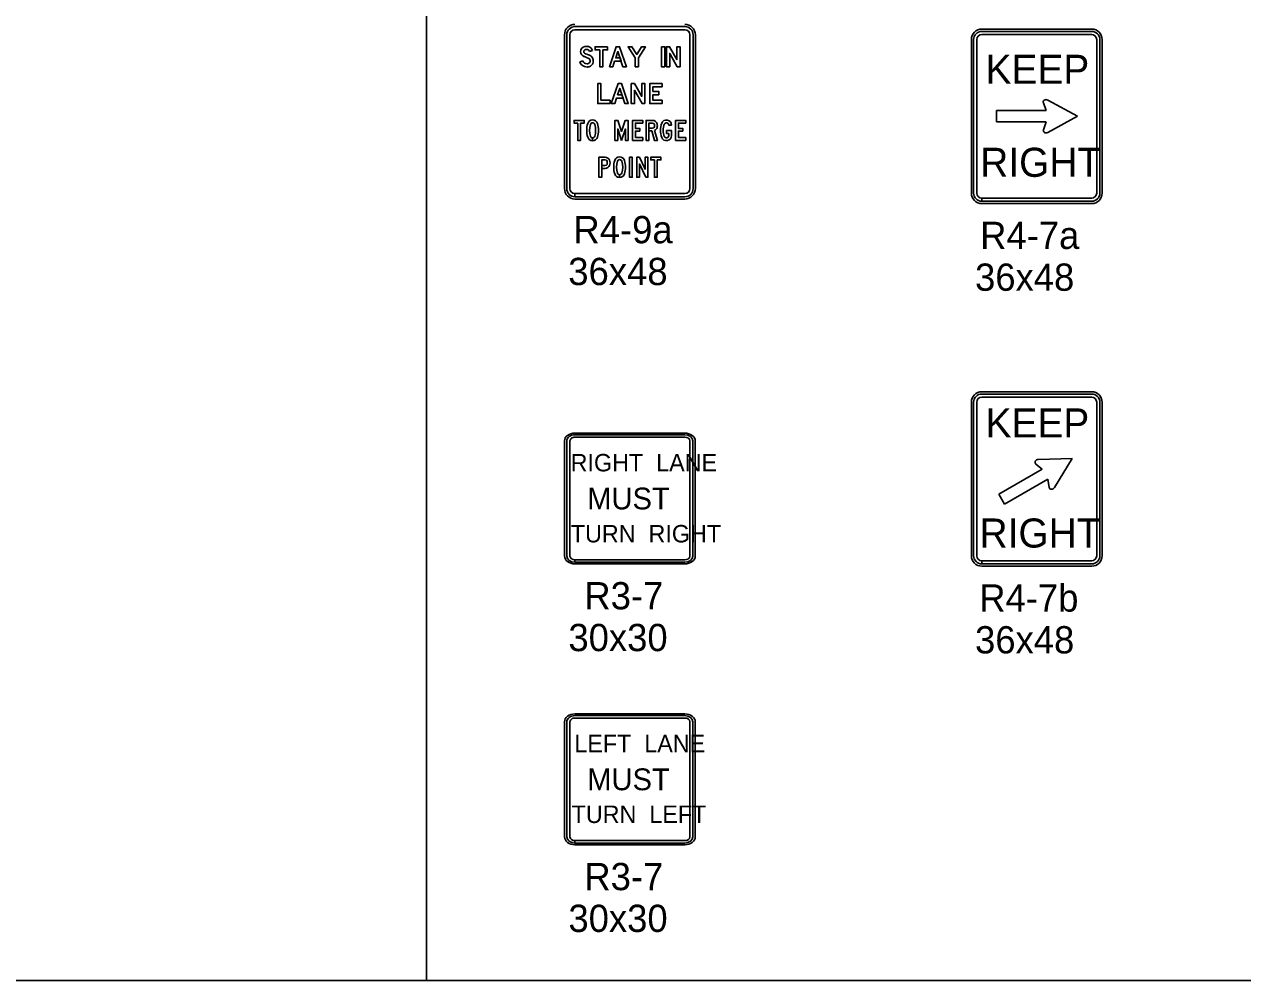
# Model space of a CAD drawing. Extents: x 1458 to 4498, y 17709 to 24109.
# Drawn here: x 3157 to 3828, y 19909 to 20435 of the extents above; entities that cross this region are included whole.
import ezdxf

# ---------------------------------------------------------------- set-up
doc = ezdxf.new("R2010")
doc.units = 0
doc.layers.add('P_ODOT_PLAN_TBlock', color=7, linetype='Continuous')
doc.layers.add('P_TRAF_TCP_General', color=7, linetype='Continuous')

msp = doc.modelspace()

# ---------------------------------------------------------------- linework, layer by layer
at = {"layer": 'P_ODOT_PLAN_TBlock'}
msp.add_line((3378.44, 20667.08), (3378.44, 19909.14), dxfattribs=at)
at = {"layer": 'P_TRAF_TCP_General'}
for p, q in [((3454.42, 20429.42), (3454.42, 20344.86)), ((3455.67, 20429.42), (3455.67, 20344.86)), ((3457.42, 20344.86), (3457.42, 20429.42)), ((3520.72, 20433.92), (3460.17, 20433.92)), ((3460.17, 20432.17), (3520.72, 20432.17)), ((3523.48, 20429.42), (3523.48, 20344.86)), ((3525.23, 20344.86), (3525.23, 20429.42)), ((3526.48, 20344.86), (3526.48, 20429.42)), ((3744.67, 20432.56), (3684.19, 20432.56)), ((3744.67, 20431.31), (3684.19, 20431.31)), ((3684.19, 20429.56), (3744.67, 20429.56)), ((3678.44, 20426.82), (3678.44, 20342.35)), ((3679.69, 20426.82), (3679.69, 20342.35)), ((3681.44, 20342.35), (3681.44, 20426.82)), ((3747.42, 20426.82), (3747.42, 20342.35)), ((3749.17, 20342.35), (3749.17, 20426.82)), ((3750.41, 20342.35), (3750.41, 20426.82)), ((3719.62, 20387.82), (3718.13, 20392)), ((3720.47, 20393.57), (3736.93, 20384.65)), ((3692.2, 20387.83), (3719.62, 20387.82)), ((3692.2, 20381.49), (3692.2, 20387.83)), ((3736.93, 20384.65), (3720.5, 20375.75)), ((3502.93, 20378.09), (3502.93, 20378.09)), ((3511.83, 20379.77), (3513.37, 20379.77)), ((3511.83, 20375.17), (3511.83, 20373.99)), ((3719.62, 20381.49), (3692.2, 20381.49)), ((3718.05, 20377.15), (3719.62, 20381.49)), ((3469.9, 20372.72), (3469.9, 20371.18)), ((3469.9, 20371.18), (3469.9, 20372.72)), ((3484.78, 20352.46), (3484.78, 20350.92)), ((3484.78, 20350.92), (3484.78, 20352.46)), ((3460.17, 20340.35), (3460.17, 20342.1)), ((3520.72, 20342.1), (3460.19, 20342.1)), ((3460.19, 20342.1), (3460.19, 20340.35)), ((3460.17, 20339.1), (3520.72, 20339.1)), ((3460.19, 20340.35), (3520.72, 20340.35)), ((3684.19, 20337.85), (3684.19, 20339.6)), ((3684.19, 20336.6), (3744.67, 20336.6)), ((3744.67, 20339.6), (3684.21, 20339.6)), ((3684.21, 20339.6), (3684.21, 20337.85)), ((3684.21, 20337.85), (3744.67, 20337.85)), ((3744.67, 20233.08), (3684.19, 20233.08)), ((3744.67, 20231.83), (3684.19, 20231.83)), ((3684.19, 20230.08), (3744.67, 20230.08)), ((3678.44, 20227.33), (3678.44, 20142.86)), ((3679.69, 20227.33), (3679.69, 20142.86)), ((3681.44, 20142.86), (3681.44, 20227.33)), ((3747.42, 20227.33), (3747.42, 20142.86)), ((3749.17, 20142.86), (3749.17, 20227.33)), ((3750.41, 20142.86), (3750.41, 20227.33)), ((3520.67, 20210.34), (3460.2, 20210.34)), ((3520.67, 20209.4), (3460.2, 20209.4)), ((3460.2, 20208.09), (3520.67, 20208.09)), ((3454.45, 20206.03), (3454.45, 20142.68)), ((3455.7, 20206.03), (3455.7, 20142.68)), ((3457.45, 20142.68), (3457.45, 20206.03)), ((3523.42, 20206.03), (3523.42, 20142.68)), ((3525.17, 20142.68), (3525.17, 20206.03)), ((3526.42, 20142.68), (3526.42, 20206.03)), ((3715.25, 20195.84), (3733.96, 20196.28)), ((3733.96, 20196.28), (3724.13, 20180.39)), ((3693.58, 20176.81), (3717.37, 20190.43)), ((3717.37, 20190.43), (3714, 20193.31)), ((3720.52, 20184.93), (3696.72, 20171.31)), ((3721.31, 20180.39), (3720.52, 20184.93)), ((3696.72, 20171.31), (3693.58, 20176.81)), ((3460.2, 20139.3), (3460.2, 20140.61)), ((3520.67, 20140.61), (3460.22, 20140.61)), ((3460.22, 20140.61), (3460.22, 20139.3)), ((3460.2, 20138.37), (3520.67, 20138.37)), ((3460.22, 20139.3), (3520.67, 20139.3)), ((3684.19, 20138.37), (3684.19, 20140.11)), ((3684.19, 20137.12), (3744.67, 20137.12)), ((3744.67, 20140.11), (3684.21, 20140.11)), ((3684.21, 20140.11), (3684.21, 20138.37)), ((3684.21, 20138.37), (3744.67, 20138.37)), ((3520.67, 20055.85), (3460.2, 20055.85)), ((3520.67, 20054.91), (3460.2, 20054.91)), ((3460.2, 20053.6), (3520.67, 20053.6)), ((3454.45, 20051.54), (3454.45, 19988.19)), ((3455.7, 20051.54), (3455.7, 19988.19)), ((3457.45, 19988.19), (3457.45, 20051.54)), ((3523.42, 20051.54), (3523.42, 19988.19)), ((3525.17, 19988.19), (3525.17, 20051.54)), ((3526.42, 19988.19), (3526.42, 20051.54)), ((3460.2, 19984.82), (3460.2, 19986.13)), ((3520.67, 19986.13), (3460.22, 19986.13)), ((3460.22, 19986.13), (3460.22, 19984.82)), ((3460.2, 19983.88), (3520.67, 19983.88)), ((3460.22, 19984.82), (3520.67, 19984.82))]:
    msp.add_line(p, q, dxfattribs=at)
for points in [[(4498.44, 21909.14), (1458.44, 21909.14), (1458.44, 19909.14), (4498.44, 19909.14)], [(3478.13, 20422.91), (3478.13, 20421.15), (3475.6, 20421.15), (3475.6, 20411.91), (3473.84, 20411.91), (3473.84, 20421.15), (3471.31, 20421.15), (3471.31, 20422.91)], [(3479.13, 20411.91), (3482.87, 20422.91), (3484.74, 20422.91), (3488.49, 20411.91), (3486.63, 20411.91), (3483.81, 20420.19), (3482.62, 20416.69), (3485, 20416.69), (3485.6, 20414.93), (3482.02, 20414.93), (3480.99, 20411.91)], [(3493.34, 20411.91), (3495.1, 20411.91), (3495.1, 20416.75), (3498.95, 20422.91), (3496.88, 20422.91), (3494.22, 20418.66), (3491.56, 20422.91), (3489.49, 20422.91), (3493.34, 20416.75)], [(3507.83, 20422.91), (3509.59, 20422.91), (3509.59, 20411.91), (3507.83, 20411.91)], [(3518.08, 20411.91), (3518.08, 20422.91), (3516.32, 20422.91), (3516.32, 20415.84), (3512.28, 20422.91), (3510.59, 20422.91), (3510.59, 20411.91), (3512.35, 20411.91), (3512.35, 20419.23), (3516.54, 20411.91)], [(3474.49, 20393.4), (3479.55, 20393.4), (3479.55, 20391.64), (3472.73, 20391.64), (3472.73, 20402.65), (3474.49, 20402.65)], [(3480.21, 20391.64), (3483.96, 20402.65), (3485.83, 20402.65), (3489.57, 20391.64), (3487.71, 20391.64), (3484.89, 20399.93), (3483.7, 20396.43), (3486.08, 20396.43), (3486.68, 20394.67), (3483.1, 20394.67), (3482.07, 20391.64)], [(3498.71, 20391.64), (3498.71, 20402.65), (3496.94, 20402.65), (3496.94, 20395.58), (3492.9, 20402.65), (3491.22, 20402.65), (3491.22, 20391.64), (3492.98, 20391.64), (3492.98, 20398.96), (3497.16, 20391.64)], [(3508.17, 20400.89), (3503.11, 20400.89), (3503.11, 20398.25), (3506.31, 20398.25), (3506.31, 20396.49), (3503.11, 20396.49), (3503.11, 20393.4), (3508.17, 20393.4), (3508.17, 20391.64), (3501.35, 20391.64), (3501.35, 20402.65), (3508.17, 20402.65)], [(3461.75, 20380.84), (3459.71, 20380.84), (3459.71, 20382.38), (3465.33, 20382.38), (3465.33, 20380.84), (3463.29, 20380.84), (3463.29, 20371.37), (3461.75, 20371.37)], [(3485.86, 20371.37), (3487.95, 20377.71), (3487.95, 20371.37), (3489.49, 20371.37), (3489.49, 20382.38), (3487.87, 20382.38), (3485.86, 20376.29), (3483.85, 20382.38), (3482.22, 20382.38), (3482.22, 20371.37), (3483.76, 20371.37), (3483.76, 20377.71)], [(3493.45, 20372.91), (3493.45, 20376.44), (3495.86, 20376.44), (3495.86, 20377.98), (3493.45, 20377.98), (3493.45, 20380.84), (3497.52, 20380.84), (3497.52, 20382.38), (3491.91, 20382.38), (3491.91, 20371.37), (3497.52, 20371.37), (3497.52, 20372.91)], [(3517.12, 20372.91), (3517.12, 20376.44), (3519.53, 20376.44), (3519.53, 20377.98), (3517.12, 20377.98), (3517.12, 20380.84), (3521.19, 20380.84), (3521.19, 20382.38), (3515.58, 20382.38), (3515.58, 20371.37), (3521.19, 20371.37), (3521.19, 20372.91)], [(3490.23, 20362.12), (3491.77, 20362.12), (3491.77, 20351.11), (3490.23, 20351.11)], [(3499.15, 20351.11), (3500.36, 20351.11), (3500.36, 20362.12), (3498.82, 20362.12), (3498.82, 20355.47), (3495.72, 20362.12), (3494.19, 20362.12), (3494.19, 20351.11), (3495.73, 20351.11), (3495.73, 20358.43)], [(3503.94, 20360.58), (3501.9, 20360.58), (3501.9, 20362.12), (3507.51, 20362.12), (3507.51, 20360.58), (3505.48, 20360.58), (3505.48, 20351.11), (3503.94, 20351.11)]]:
    msp.add_lwpolyline(points, close=True, dxfattribs=at)
for points in [[(3468.16, 20420.32), (3469.83, 20420.88)], [(3464.47, 20415.11), (3462.82, 20414.49)], [(3502.93, 20380.84), (3500.94, 20380.84), (3500.94, 20371.37), (3499.39, 20371.37), (3499.39, 20382.38), (3502.93, 20382.38)], [(3504.02, 20376.79), (3505.56, 20371.37), (3503.96, 20371.37), (3502.48, 20376.55), (3500.94, 20376.55), (3500.94, 20378.09), (3502.93, 20378.09)], [(3513.37, 20373.99), (3513.37, 20376.71), (3510.62, 20376.71), (3510.62, 20375.17), (3511.83, 20375.17)], [(3476.88, 20362.12), (3473.39, 20362.12), (3473.39, 20351.11), (3474.93, 20351.11), (3474.93, 20360.58), (3476.88, 20360.58)], [(3476.88, 20357.49), (3474.93, 20357.49), (3474.93, 20355.95), (3476.88, 20355.95)]]:
    msp.add_lwpolyline(points, dxfattribs=at)
for centre, radius, start, end in [((3460.17, 20429.42), 5.75, 90, 180), ((3460.17, 20429.42), 4.5, 90, 180), ((3460.17, 20429.42), 2.75, 90, 180), ((3520.72, 20429.42), 5.75, 0, 90), ((3520.72, 20429.42), 4.5, 0, 90), ((3520.72, 20429.42), 2.75, 0, 90), ((3684.19, 20426.82), 5.75, 90, 180), ((3684.19, 20426.82), 4.5, 90, 180), ((3684.19, 20426.82), 2.75, 90, 180), ((3744.67, 20426.82), 5.75, 0, 90), ((3744.67, 20426.82), 4.5, 0, 90), ((3744.67, 20426.82), 2.75, 0, 90), ((3502.93, 20379.79), 2.59, 13.88654, 90), ((3502.93, 20379.79), 1.05, 13.88654, 90), ((3502.93, 20379.13), 1.05, 270, 346.11346), ((3501.6, 20379.46), 2.42, 346.11346, 13.88654), ((3502.93, 20379.13), 2.59, 294.82206, 346.11346), ((3501.6, 20379.46), 3.96, 346.11346, 13.88654), ((3476.88, 20359.53), 2.59, 21.1002, 90), ((3476.88, 20359.53), 1.05, 21.1002, 90), ((3476.88, 20358.54), 1.05, 270, 338.8998), ((3476.88, 20358.54), 2.59, 270, 338.8998), ((3475.59, 20359.04), 2.42, 338.89981, 21.1002), ((3475.59, 20359.04), 3.96, 338.8998, 21.10019), ((3460.17, 20344.86), 5.75, 180, 270), ((3460.17, 20344.86), 4.5, 180, 270), ((3460.17, 20344.86), 2.75, 180, 270), ((3520.72, 20344.86), 4.5, 270, 0), ((3520.72, 20344.86), 2.75, 270, 0), ((3520.72, 20344.86), 5.75, 270, 0), ((3684.19, 20342.35), 5.75, 180, 270), ((3684.19, 20342.35), 4.5, 180, 270), ((3684.19, 20342.35), 2.75, 180, 270), ((3744.67, 20342.35), 4.5, 270, 0), ((3744.67, 20342.35), 2.75, 270, 0), ((3744.67, 20342.35), 5.75, 270, 0), ((3684.19, 20227.33), 5.75, 90, 180), ((3684.19, 20227.33), 4.5, 90, 180), ((3684.19, 20227.33), 2.75, 90, 180), ((3744.67, 20227.33), 5.75, 0, 90), ((3744.67, 20227.33), 4.5, 0, 90), ((3744.67, 20227.33), 2.75, 0, 90), ((3684.19, 20142.86), 5.75, 180, 270), ((3684.19, 20142.86), 4.5, 180, 270), ((3684.19, 20142.86), 2.75, 180, 270), ((3744.67, 20142.86), 4.5, 270, 0), ((3744.67, 20142.86), 2.75, 270, 0), ((3744.67, 20142.86), 5.75, 270, 0)]:
    msp.add_arc(centre, radius, start, end, dxfattribs=at)
for centre, major_axis, ratio, start_param, end_param in [((3466.21, 20420.14), (0, 2.93), 0.999995, 0.175685, 1.570796), ((3466.53, 20418.32), (0, 4.78), 0.999995, 0.090794, 0.175685), ((3466.68, 20416.7), (0, 6.4), 0.999995, 6.283185, 6.373979), ((3466.68, 20419.6), (0, 3.5), 0.999995, 6.012094, 6.283185), ((3466.75, 20419.85), (0, 3.25), 0.999995, 5.034126, 6.012094), ((3465.99, 20420.14), (0, 2.71), 0.999995, 1.570796, 2.627164), ((3468.48, 20424.54), (0, 7.77), 0.999995, 2.627164, 2.834816), ((3466.21, 20420.14), (0, 1.17), 0.999995, 0.175685, 1.570796), ((3465.99, 20420.14), (0, 0.952), 0.999995, 1.570796, 2.627164), ((3468.48, 20424.54), (0, 6.01), 0.999995, 2.627164, 2.834816), ((3466.53, 20418.32), (0, 3.01), 0.999995, 0.090794, 0.175685), ((3462.54, 20405.79), (0, 11.9), 0.999995, 5.820582, 5.976409), ((3466.68, 20416.7), (0, 4.64), 0.999995, 0, 0.090794), ((3462.54, 20405.79), (0, 13.66), 0.999995, 5.820582, 5.976409), ((3466.68, 20419.6), (0, 1.74), 0.999995, 6.012094, 6.283185), ((3466.75, 20419.85), (0, 1.48), 0.999995, 5.034126, 6.012094), ((3467.33, 20415.39), (0, 1.17), 0.999995, 5.010707, 5.820582), ((3466.32, 20415.08), (0, 2.22), 0.999995, 4.712389, 5.010707), ((3467.33, 20415.39), (0, 2.93), 0.999995, 5.010707, 5.820582), ((3466.32, 20415.08), (0, 3.98), 0.999995, 4.712389, 5.010707), ((3466.83, 20416), (0, 4.28), 0.999995, 1.931277, 3.141593), ((3466.83, 20416), (0, 2.52), 0.999995, 1.931277, 3.141593), ((3466.83, 20415.54), (0, 2.06), 0.999995, 3.141593, 3.672524), ((3466.83, 20415.54), (0, 3.82), 0.999995, 3.141593, 3.672524), ((3467.23, 20414.86), (0, 1.27), 0.999995, 3.672524, 4.331279), ((3466.67, 20415.08), (0, 1.88), 0.999995, 4.331279, 4.712389), ((3467.23, 20414.86), (0, 3.03), 0.999995, 3.672524, 4.331279), ((3466.67, 20415.08), (0, 3.64), 0.999995, 4.331279, 4.712389), ((3719.58, 20392.52), (1.59, 0), 0.8, 0.975433, 3.563107), ((3469.9, 20379.77), (0, 2.81), 0.999996, 5.014824, 7.551546), ((3510.57, 20379.77), (0, 2.81), 0.999992, 4.712389, 7.477539), ((3479.16, 20376.88), (0, 12.51), 0.999996, 1.268361, 1.873232), ((3479.16, 20376.88), (0, 10.97), 0.999996, 1.268361, 1.873232), ((3469.9, 20379.77), (0, 1.27), 0.999996, 5.014824, 7.551546), ((3460.63, 20376.88), (0, 10.97), 0.999996, 4.409954, 5.014824), ((3460.63, 20376.88), (0, 12.51), 0.999996, 4.409954, 5.014824), ((3517.88, 20376.88), (0, 10.67), 0.999992, 1.194353, 1.947239), ((3517.88, 20376.88), (0, 9.13), 0.999992, 1.194353, 1.947239), ((3510.57, 20379.77), (0, 1.27), 0.999992, 4.712389, 7.477539), ((3719.58, 20376.79), (1.59, 0), 0.8, 2.8592, 5.330358), ((3469.9, 20373.99), (0, 2.81), 0.999996, 1.873232, 3.141593), ((3469.9, 20373.99), (0, 1.27), 0.999996, 1.873232, 3.141593), ((3469.9, 20373.99), (0, 1.27), 0.999996, 3.142027, 4.409954), ((3469.9, 20373.99), (0, 2.81), 0.999996, 3.141789, 4.409954), ((3510.57, 20373.99), (0, 2.81), 0.999992, 1.947239, 4.712389), ((3510.57, 20373.99), (0, 1.27), 0.999992, 1.947239, 4.712389), ((3484.78, 20359.5), (0, 2.81), 0.999997, 5.014824, 7.551546), ((3494.04, 20356.61), (0, 12.51), 0.999997, 1.268361, 1.873232), ((3494.04, 20356.61), (0, 10.97), 0.999997, 1.268361, 1.873232), ((3484.78, 20359.5), (0, 1.27), 0.999997, 5.014824, 7.551546), ((3475.52, 20356.61), (0, 10.97), 0.999997, 4.409954, 5.014824), ((3475.52, 20356.61), (0, 12.51), 0.999997, 4.409954, 5.014824), ((3484.78, 20353.72), (0, 2.81), 0.999997, 1.873232, 3.141593), ((3484.78, 20353.72), (0, 1.27), 0.999997, 1.873232, 3.141593), ((3484.78, 20353.72), (0, 1.27), 0.999997, 3.142027, 4.409954), ((3484.78, 20353.72), (0, 2.81), 0.999997, 3.141789, 4.409954), ((3460.2, 20206.03), (5.75, 0), 0.75, 1.570796, 3.141593), ((3460.2, 20206.03), (4.5, 0), 0.75, 1.570796, 3.141593), ((3460.2, 20206.03), (2.75, 0), 0.75, 1.570796, 3.141593), ((3520.67, 20206.03), (5.75, 0), 0.75, 0, 1.570796), ((3520.67, 20206.03), (4.5, 0), 0.75, 0, 1.570796), ((3520.67, 20206.03), (2.75, 0), 0.75, 0, 1.570796), ((3715, 20194.48), (1.38, 0.79), 0.8, 0.975433, 3.563107), ((3722.81, 20180.84), (1.38, 0.79), 0.8, 2.8592, 5.330358), ((3460.2, 20142.68), (5.75, 0), 0.75, 3.141593, 4.712389), ((3460.2, 20142.68), (4.5, 0), 0.75, 3.141593, 4.712389), ((3460.2, 20142.68), (2.75, 0), 0.75, 3.141593, 4.712389), ((3520.67, 20142.68), (4.5, 0), 0.75, 4.712389, 6.283185), ((3520.67, 20142.68), (2.75, 0), 0.75, 4.712389, 6.283185), ((3520.67, 20142.68), (5.75, 0), 0.75, 4.712389, 6.283185), ((3460.2, 20051.54), (5.75, 0), 0.75, 1.570796, 3.141593), ((3460.2, 20051.54), (4.5, 0), 0.75, 1.570796, 3.141593), ((3460.2, 20051.54), (2.75, 0), 0.75, 1.570796, 3.141593), ((3520.67, 20051.54), (5.75, 0), 0.75, 0, 1.570796), ((3520.67, 20051.54), (4.5, 0), 0.75, 0, 1.570796), ((3520.67, 20051.54), (2.75, 0), 0.75, 0, 1.570796), ((3460.2, 19988.19), (5.75, 0), 0.75, 3.141593, 4.712389), ((3460.2, 19988.19), (4.5, 0), 0.75, 3.141593, 4.712389), ((3460.2, 19988.19), (2.75, 0), 0.75, 3.141593, 4.712389), ((3520.67, 19988.19), (4.5, 0), 0.75, 4.712389, 6.283185), ((3520.67, 19988.19), (2.75, 0), 0.75, 4.712389, 6.283185), ((3520.67, 19988.19), (5.75, 0), 0.75, 4.712389, 6.283185)]:
    msp.add_ellipse(centre, major_axis=major_axis, ratio=ratio, start_param=start_param, end_param=end_param, dxfattribs=at)

# ---------------------------------------------------------------- texts
for s, height, p in [('KEEP', 15.994, (3686.27, 20402.47)), ('RIGHT', 15.994, (3683.33, 20351.31)), ('R4-9a', 15.012, (3459.32, 20314.75)), ('R4-7a', 14.994, (3683.25, 20311.61)), ('36x48', 15.012, (3456.51, 20291.74)), ('36x48', 14.994, (3680.45, 20288.62)), ('KEEP', 15.994, (3686.27, 20207.93)), ('RIGHT  LANE', 9.6, (3457.83, 20189.26)), ('MUST', 11.995, (3466.94, 20168.35)), ('RIGHT', 15.994, (3682.95, 20147.36)), ('TURN  RIGHT', 9.6, (3457.91, 20150.19)), ('R3-7', 14.994, (3465.37, 20113.38)), ('R4-7b', 14.994, (3682.76, 20112.13)), ('30x30', 14.994, (3456.6, 20090.38)), ('36x48', 14.994, (3680.45, 20089.13)), ('LEFT  LANE', 9.6, (3459.85, 20034.76)), ('MUST', 11.995, (3466.94, 20013.87)), ('TURN  LEFT', 9.6, (3458.37, 19995.84)), ('R3-7', 14.994, (3465.37, 19958.89)), ('30x30', 14.994, (3456.6, 19935.9))]:
    msp.add_text(s, height=height, dxfattribs=at).set_placement(p)

doc.saveas('drawing.dxf')
